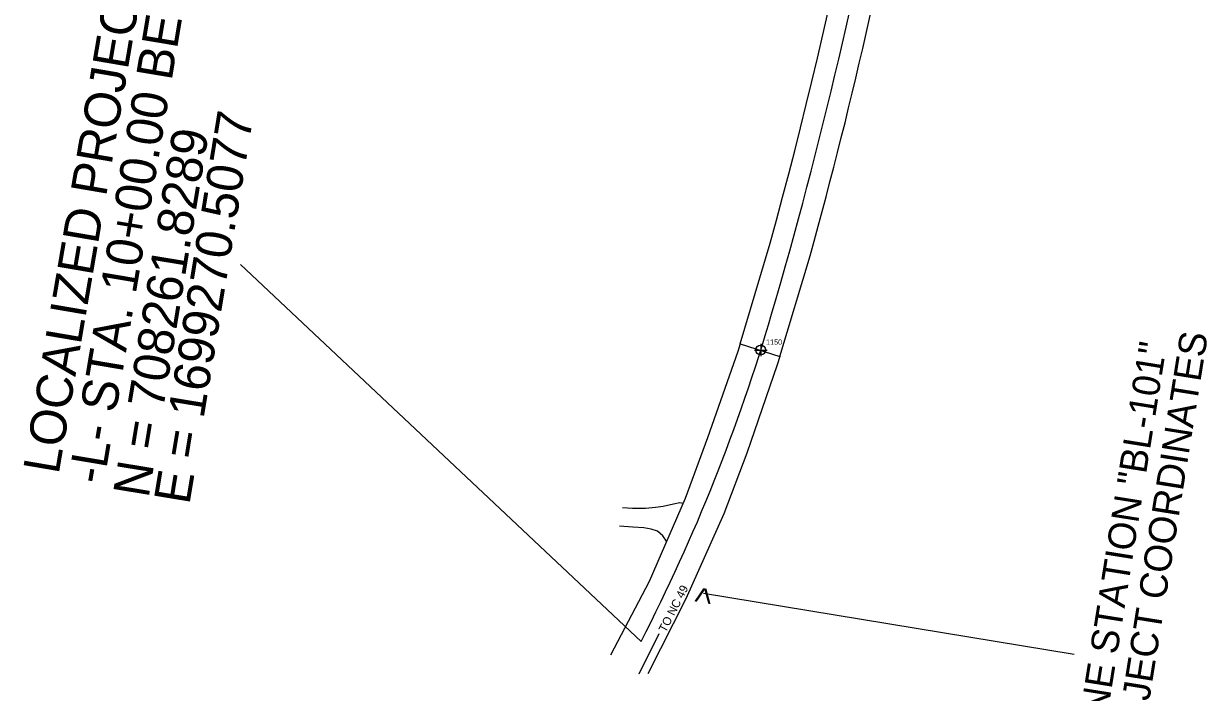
# Model space of a CAD drawing. Extents: x 1698609 to 1700392, y 707479 to 710040.
# Drawn here: x 1698977 to 1699540, y 708238 to 708556 of the extents above; entities that cross this region are included whole.
import ezdxf

# ---------------------------------------------------------------- set-up
doc = ezdxf.new("R2010")
doc.units = 0
for name, color, linetype in [('Cogo Default Point CELL', 7, 'Continuous'), ('COGO Default Point Number', 7, 'Continuous'), ('CTL Sheet Notes CELL', 7, 'Continuous'), ('CTL Sheet Text', 7, 'Continuous'), ('Default', 7, 'Continuous'), ('Exist Horizontal Baseline Alignment Station Label', 7, 'Continuous'), ('Exist Roads EOP', 7, 'Continuous'), ('Exist Roads EOP Leader', 7, 'Continuous'), ('Exist Roads EOP Other', 7, 'Continuous'), ('Exist Roads EOP Text', 7, 'Continuous'), ('Old_Level_2', 7, 'Continuous'), ('Prop Horizontal Alignment', 7, 'Continuous')]:
    doc.layers.add(name, color=color, linetype=linetype)

msp = doc.modelspace()

# ---------------------------------------------------------------- linework, layer by layer
at = {"layer": 'Cogo Default Point CELL'}
for points in [[(1699327.41, 708403.42), (1699327.41, 708400.42)], [(1699324.41, 708400.42), (1699327.41, 708400.42)], [(1699327.41, 708400.42), (1699330.41, 708400.42)], [(1699327.41, 708400.42), (1699327.41, 708397.42)]]:
    msp.add_lwpolyline(points, dxfattribs=at)
msp.add_circle((1699327.41, 708400.42), 2.34, dxfattribs=at)
at = {"layer": 'Default'}
for p, q in [((1699317.59, 708403.33), (1699331.83, 708451.27)), ((1699336.52, 708397.37), (1699350.89, 708445.24)), ((1699317.59, 708403.33), (1699336.52, 708397.37))]:
    msp.add_line(p, q, dxfattribs=at)
for centre, radius, start, end in [((1697132.82, 709061.2), 2282.04, 344.49766, 353.61848), ((1697124.94, 709062.69), 2310, 344.49666, 350.26654)]:
    msp.add_arc(centre, radius, start, end, dxfattribs=at)
at = {"layer": 'Exist Horizontal Baseline Alignment Station Label'}
for p, q in [((1699270.51, 708261.83), (1699079.87, 708441.13)), ((1699300.22, 708284.8), (1699476.46, 708255.68))]:
    msp.add_line(p, q, dxfattribs=at)
at = {"layer": 'Exist Roads EOP'}
for points in [[(1699317.59, 708403.33), (1699316.49, 708399.68), (1699302.08, 708358.62), (1699291.44, 708329.76), (1699274.25, 708290.35), (1699255.98, 708255.28)], [(1699336.52, 708397.37), (1699335.28, 708393.42), (1699320.77, 708351.4), (1699309.77, 708322.46), (1699291.82, 708282.07), (1699273.74, 708246.39)]]:
    msp.add_lwpolyline(points, dxfattribs=at)
at = {"layer": 'Exist Roads EOP Leader'}
msp.add_lwpolyline([(1699269.56, 708246.36), (1699279.05, 708265.55)], dxfattribs=at)
at = {"layer": 'Exist Roads EOP Other'}
for p, q in [((1699266.41, 708325.04), (1699261.69, 708325.37)), ((1699272.58, 708325.01), (1699266.41, 708325.04)), ((1699277.34, 708325.44), (1699272.58, 708325.01)), ((1699280.92, 708326.01), (1699277.34, 708325.44)), ((1699285.86, 708327.05), (1699280.92, 708326.01)), ((1699288.93, 708327.71), (1699285.86, 708327.05)), ((1699290.44, 708327.47), (1699288.93, 708327.71)), ((1699266.56, 708316.2), (1699260.27, 708316.65)), ((1699271.79, 708315.78), (1699266.56, 708316.2)), ((1699275.32, 708315.24), (1699271.79, 708315.78)), ((1699278.22, 708314.19), (1699275.32, 708315.24)), ((1699280.88, 708311.95), (1699278.22, 708314.19)), ((1699282.59, 708309.46), (1699280.88, 708311.95))]:
    msp.add_line(p, q, dxfattribs=at)
at = {"layer": 'Prop Horizontal Alignment'}
for centre, radius, start, end in [((1697124.94, 709062.69), 2300, 343.70663, 356.20849), ((1698486.49, 708664.71), 881.47, 332.80277, 343.70663)]:
    msp.add_arc(centre, radius, start, end, dxfattribs=at)

# ---------------------------------------------------------------- texts
at = {"layer": 'COGO Default Point Number'}
msp.add_text('1150', height=2.5, dxfattribs=at).set_placement((1699329.91, 708402.92))
at = {"layer": 'CTL Sheet Notes CELL'}
msp.add_text('>', height=10.58, rotation=80.4269, dxfattribs=at).set_placement((1699304.55, 708278.71))
at = {"layer": 'CTL Sheet Text'}
for s, height, rotation, p in [('LOCALIZED PROJECT COORDINATES', 17.1764, 80.3069, (1698993.41, 708340.91)), ('E = 1699270.5077', 17.1764, 80.6527, (1699055.6, 708326.47)), ('N = 708261.8289', 17.1764, 80.6527, (1699036.19, 708329.66)), ('LOCALIZED PROJECT COORDINATES', 13.1041, 80.9052, (1699490, 708094.6)), ('NCDOT BASELINE STATION "BL-101"', 13.1041, 80.8935, (1699471.92, 708099.46))]:
    msp.add_text(s, height=height, rotation=rotation, dxfattribs=at).set_placement(p)
at = {"layer": 'Exist Roads EOP Text'}
msp.add_text('TO NC 49', height=4, rotation=63.1317, dxfattribs=at).set_placement((1699282.21, 708265.78))
at = {"layer": 'Old_Level_2'}
msp.add_text('-L- STA. 10+00.00 BEGIN TIP PROJECT B-4799', height=17.1764, rotation=80.4578, dxfattribs=at).set_placement((1699014.86, 708336.09))

doc.saveas('drawing.dxf')
